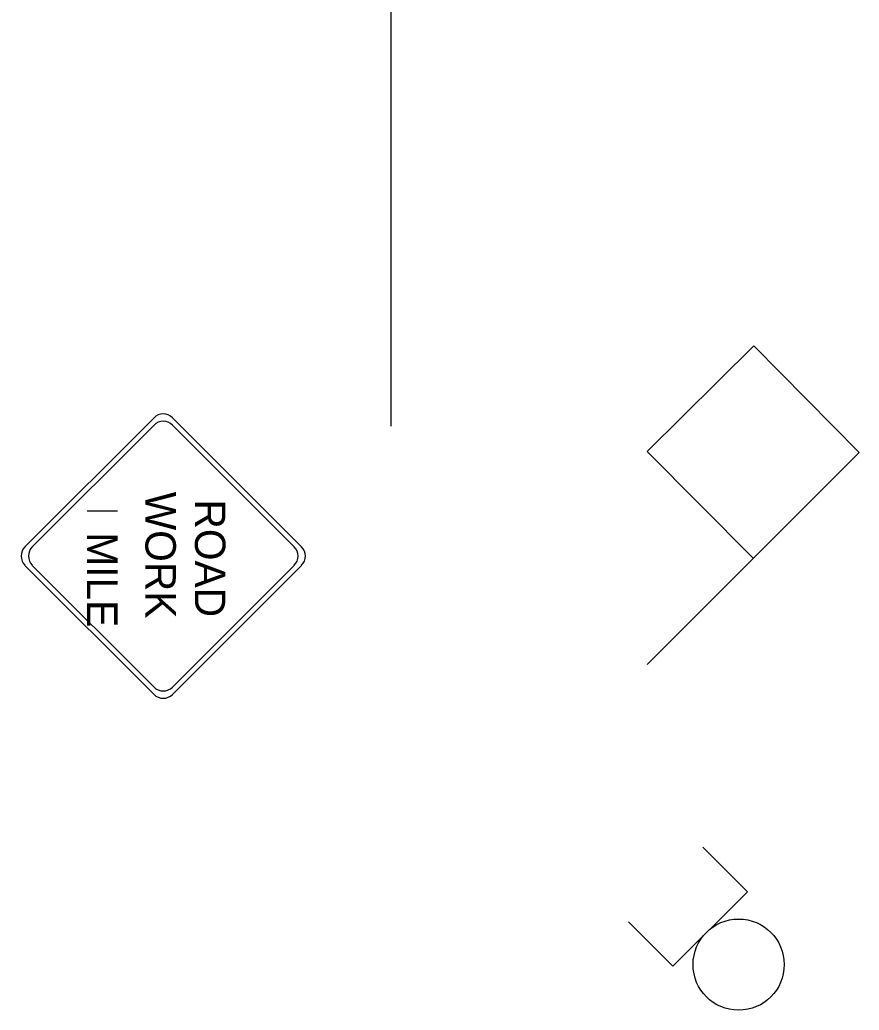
# Model space of a CAD drawing. Extents: x 2155255 to 2162649, y 140388 to 141878.
# Drawn here: x 2156597.5 to 2156673.5, y 140738.2 to 140827.8 of the extents above; entities that cross this region are included whole.
import ezdxf

# ---------------------------------------------------------------- set-up
doc = ezdxf.new("R2010")
doc.units = 0
for name, color, linetype in [('5', 7, 'Continuous'), ('Default', 7, 'Continuous'), ('PR_Dimensions1', 7, 'Continuous'), ('PR_Traffic_Control_Devices_Temp', 7, 'Continuous')]:
    doc.layers.add(name, color=color, linetype=linetype)

# ---------------------------------------------------------------- blocks, each defined once
blk = doc.blocks.new('Cw20-1')
at = {"layer": '5'}
for p, q in [((0.318, 3.005), (2.651, 5.339)), ((5.338, 3.005), (3.005, 5.339)), ((2.651, 0.318), (0.318, 2.652)), ((3.005, 0.318), (5.338, 2.652))]:
    blk.add_line(p, q, dxfattribs=at)
for centre, start, end in [((2.828, 5.162), 45, 135), ((0.495, 2.828), 135, 225), ((5.162, 2.828), 315, 45), ((2.828, 0.495), 225, 315)]:
    blk.add_arc(centre, 0.25, start, end, dxfattribs=at)
at = {"layer": 'Default'}
for p, q in [((0.177, 3.005), (2.651, 5.48)), ((5.48, 3.005), (3.005, 5.48)), ((2.651, 0.177), (0.177, 2.652)), ((3.005, 0.177), (5.48, 2.652)), ((1.961, 1.37), (1.961, 1.953))]:
    blk.add_line(p, q, dxfattribs=at)
for centre, start, end in [((2.828, 5.303), 45, 135), ((0.353, 2.828), 135, 225), ((5.303, 2.828), 315, 45), ((2.828, 0.354), 225, 315)]:
    blk.add_arc(centre, 0.25, start, end, dxfattribs=at)
for s, p in [('ROAD', (1.743, 3.436)), ('WORK', (1.595, 2.487)), ('MILE', (2.372, 1.369))]:
    blk.add_text(s, height=0.5833, dxfattribs=at).set_placement(p)
blk = doc.blocks.new('FLSHFLAG')
at = {"layer": 'Default'}
for p, q in [((-1.202, 14.125), (0.838, 16.147)), ((0.838, 16.147), (4.9, 12.085)), ((0.819, 12.085), (-1.202, 14.125)), ((0.819, 12.085), (2.86, 14.106)), ((9.258, 14.004), (8.403, 13.149)), ((9.258, 14.004), (10.685, 12.576)), ((10.685, 12.576), (9.831, 11.722))]:
    blk.add_line(p, q, dxfattribs=at)
blk.add_circle((10.653, 13.836), 0.873, dxfattribs=at)

msp = doc.modelspace()

# ---------------------------------------------------------------- linework, layer by layer
at = {"layer": 'PR_Dimensions1'}
msp.add_line((2156631.057, 140901.561), (2156631.057, 140791.058), dxfattribs=at)

# ---------------------------------------------------------------- block references
at = {"layer": 'PR_Traffic_Control_Devices_Temp', "xscale": 4.7244, "yscale": 4.7244, "rotation": -90.00000000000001}
for name, p in [('FLSHFLAG', (2156597.186, 140792.626)), ('Cw20-1', (2156597.09, 140792.643))]:
    msp.add_blockref(name, p, dxfattribs=at)

doc.saveas('drawing.dxf')
